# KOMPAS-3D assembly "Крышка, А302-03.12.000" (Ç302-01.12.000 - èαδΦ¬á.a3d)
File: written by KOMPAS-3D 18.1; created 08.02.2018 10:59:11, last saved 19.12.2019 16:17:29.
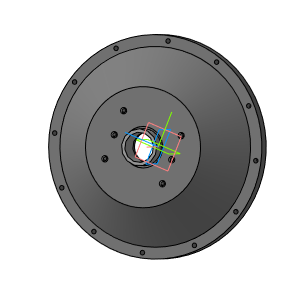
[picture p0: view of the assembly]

Document properties: Автор: Милов; Полное имя файла: D:\Мембранные насосы\Мембранный электропривод\А302-00.00.000 - ASTRA-302 (МЭ200)\3Д ПВХ\А302-01.12.000 - Крышка.a3d

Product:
- Part/product: Крышка  | designation А302-03.12.000  | pos. 0
    Материал: Полипропилен  ГОСТ 26996-86 (density 900 kg/m3)
    Масса: 2.93292
    Раздел спецификации: Сборочные единицы
    Форматы листов документа: A3
    source file: ..\..\А302-03.00.000 - ASTRA-302 (МЭ200)\А302-03.12.000 - Крышка.cdw, ..\Чертежи Полипропилен\А302-03.12.000 - Крышка.cdw
  - Component [detail]: ART. 9058 ВТУЛКА РЕЗЬБОВАЯ С ВНЕШН. И ВНУТР. РЕЗЬБОЙ M6 / M10 X 14 ММ А1-НЕРЖ  | qty 6  | pos. 28  | Масса: 0.00577673; Раздел спецификации: Детали; source file: Втулка резьбовая М6 (шт.) Alutech.m3d
  - Component [detail]: Крышка  | designation А302-03.12.001  | pos. 14
      Материал: Поливинилхлорид (density 1350 kg/m3)
      Масса: 2.71786
      Раздел спецификации: Детали
      Форматы листов документа: 2xA3
      Примечание: @100~)2xA3
      source file: ..\Чертежи Полипропилен\А302-03.12.001 - Крышка.cdw, А302-01.12.001 - Крышка.m3d
  - Component [detail]: Труба полипропиленовая 50*4,6  | designation PP  | pos. 12  | Масса: 0.149473; Раздел спецификации: Детали; source file: ..\..\..\..\1 ПКИ 3D\ПВХ фитинги, трубы\Труба PVC-U 50 3,7.m3d
- Part/product: Крышка  | designation А302-01.12.000  | pos. 0
    Материал: Полипропилен  ГОСТ 26996-86 (density 900 kg/m3)
    Масса: 2.54616
    Раздел спецификации: Сборочные единицы
    Форматы листов документа: A3
    source file: А302-01.12.000 - Крышка.cdw
  - Component [detail]: Крышка  | designation А302-01.12.001  | pos. 0
      Материал: Поливинилхлорид (density 1350 kg/m3)
      Масса: 2.45398
      Раздел спецификации: Детали
      Форматы листов документа: 2xA3
      Примечание: @100~)2xA3
      source file: А302-01.12.001 - Крышка.cdw, А302-01.12.001 - Крышка.m3d
  - Component [detail]: Труба ПВХ PN10 50х2,4  | pos. 2  | Масса: 0.340305; Раздел спецификации: Прочие изделия; Примечание: мм; source file: Отработка\Труба ПВХ PN10 50х2,4.m3d
  - Component [detail]: Труба ПВХ PN10 50х2,4  | pos. 2  | Масса: 0.340305; Раздел спецификации: Прочие изделия; source file: Отработка\Труба ПВХ PN10 50х2,4.m3d
- Part/product: Крышка  | designation А302-02.12.000  | pos. 0
    Материал: Полипропилен  ГОСТ 26996-86 (density 900 kg/m3)
    Масса: 2.64473
    Раздел спецификации: Сборочные единицы
    Форматы листов документа: A3
  - Component [detail]: Крышка  | designation А302-02.12.001  | pos. 14
      Материал: Поливинилхлорид (density 1350 kg/m3)
      Масса: 2.64473
      Раздел спецификации: Детали
      Форматы листов документа: 2xA3
      Примечание: @100~)2xA3
      source file: ..\Чертежи ПВХ\А302-02.12.001 - Крышка.cdw, А302-01.12.001 - Крышка.m3d, А302-02.00.000 - ASTRA-302 (МЭ200)\А302-02.12.001 - Крышка.cdw

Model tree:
1. Эскиз:1
2. Вырезать элемент вращения:1
     Угол 1 = 360
3. Скругление:1  (with: Вырезать элемент вращения:1, Операция выдавливания:9, Вырезать элемент выдавливания:3, Операция выдавливания:2)  (labels: Полипропилен  ГОСТ 26996-86)
     Радиус = 1
4. Эскиз:3  (with: Элемент выдавливания:44)
5. Элемент выдавливания:1
     Расстояние 1 = 151; Расстояние 2 = 151
6. Эскиз:5  (with: Элемент выдавливания:1)
7. Элемент выдавливания:2
     Расстояние 2 = 23
8. Эскиз:9  (with: Элемент выдавливания:2)
9. Элемент выдавливания:3
     Расстояние 2 = 70
10. Фаска:1  (with: Элемент выдавливания:3)
     Угол = 45; Длина 1 = 11; Длина 2 = 11
11. Массив по сетке:2  (with: Элемент выдавливания:20, Элемент выдавливания:1, Отверстие:7, Операция вращения:2)  (labels: Полипропилен  ГОСТ 26996-86)  (6 pattern instances)
     Шаг 1 = 88; Угол раствора = 90; Шаг 2 = 35; Расстояние = 1

Referenced files in D:\Мембранные насосы\Мембранный электропривод\А302-00.00.000 - ASTRA-302 (МЭ200)\3Д ПВХ\: А302-01.12.001 - Крышка.m3d, А302-01.12.001 - Крышка.cdw, Втулка резьбовая М6 (шт.) Alutech.m3d, А302-01.12.000 - Крышка.cdw, А302-01.11.000 - Крышка рабочей камеры.a3d
Referenced files in D:\Мембранные насосы\Мембранный электропривод\А302-00.00.000 - ASTRA-302 (МЭ200)\3Д ПВХ\Отработка\: Труба ПВХ PN10 50х2,4.m3d
Referenced files in D:\Мембранные насосы\Мембранный электропривод\А302-00.00.000 - ASTRA-302 (МЭ200)\3Д ПВХ\А302-02.00.000 - ASTRA-302 (МЭ200)\: А302-02.12.001 - Крышка.cdw
Referenced files in D:\Мембранные насосы\Мембранный электропривод\А302-00.00.000 - ASTRA-302 (МЭ200)\Чертежи ПВХ\: А302-02.12.001 - Крышка.cdw
Referenced files in D:\Мембранные насосы\Мембранный электропривод\А302-00.00.000 - ASTRA-302 (МЭ200)\3Д ПВХ\..\Чертежи Полипропилен\: А302-03.12.001 - Крышка.cdw
Referenced files in D:\1 ПКИ 3D\ПВХ фитинги, трубы\: Труба PVC-U 50 3,7.m3d
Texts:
  @100~)2xA3
  Крышка рабочей камеры
  Корпус со встроенными стаканами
